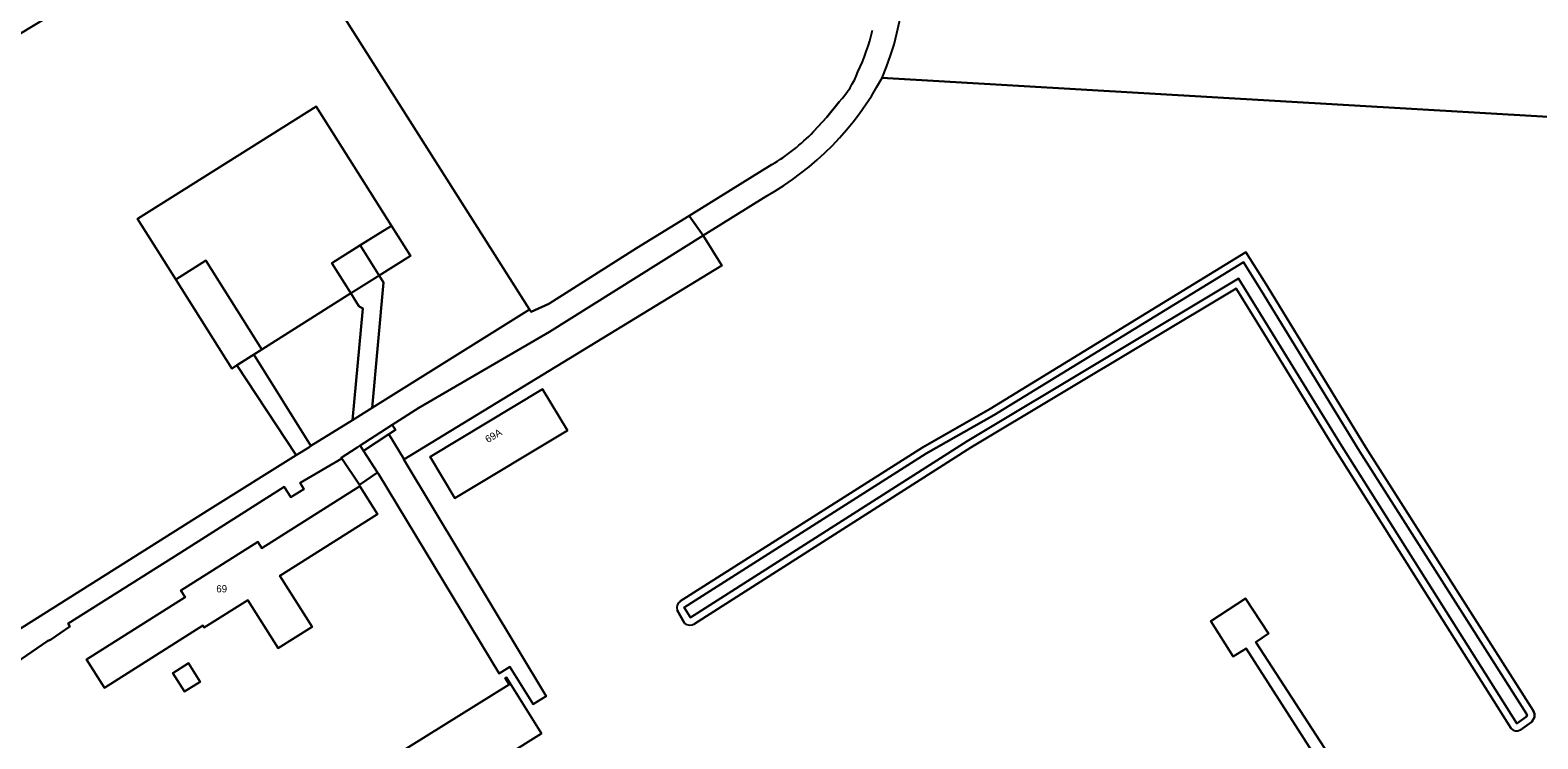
# Model space of a CAD drawing. Extents: x 158132 to 159664, y 385256 to 387218.
# Drawn here: x 158829.4 to 159037.8, y 386709.7 to 386807.7 of the extents above; entities that cross this region are included whole.
import ezdxf

# ---------------------------------------------------------------- set-up
doc = ezdxf.new("R2010")
doc.units = 0
for name, color, linetype in [('IMGEO_Gemengd_bos', 7, 'Continuous'), ('IMGEO_Groenvoorziening', 7, 'Continuous'), ('IMGEO_Loofbos', 7, 'Continuous'), ('IMGEO_Oever', 7, 'Continuous'), ('IMGEO_Open_loods', 7, 'Continuous'), ('IMGEO_Pand', 7, 'Continuous'), ('IMGEO_Pand_nummerreeks', 7, 'Continuous'), ('IMGEO_Pand_overbouw', 7, 'Continuous'), ('IMGEO_Parkeervlak_halfverhard', 7, 'Continuous'), ('IMGEO_Voetpad_gesloten', 7, 'Continuous'), ('IMGEO_Voetpad_halfverhard', 7, 'Continuous'), ('IMGEO_Voetpad_open', 7, 'Continuous'), ('IMGEO_Waterloop', 7, 'Continuous')]:
    doc.layers.add(name, color=color, linetype=linetype)

msp = doc.modelspace()

# ---------------------------------------------------------------- linework, layer by layer
at = {"layer": 'IMGEO_Gemengd_bos'}
for points in [[(158930.26, 386865.42), (158925.99, 386869.59), (158911.22, 386883.16), (158906.82, 386886.96), (158900.17, 386891.87), (158894.2, 386895.53), (158891.64, 386896.76), (158858.32, 386912.48), (158853.56, 386909.63), (158822.62, 386892.56), (158822.06, 386892.22), (158822.53, 386891.44), (158853.93, 386839), (158812.25, 386812.1), (158804.8, 386806.61), (158774.03, 386787.05), (158779.74, 386777.99), (158861.47, 386827.47), (158898.45, 386769.08), (158898.66, 386768.76), (158901.14, 386769.86), (158913.25, 386777.55), (158920.51, 386782.03), (158931.97, 386789.1)], [(158947.18, 386801.12), (159066.06, 386794.15), (159080.08, 386771.7), (159078.25, 386775.14), (159074.93, 386782.92), (159071.31, 386789.11), (159067.59, 386795.06), (159055.81, 386813.89), (159031.24, 386853.2), (159000, 386903.6)], [(159084.23, 386763.92), (159080.08, 386771.7), (159066.06, 386794.15), (158947.18, 386801.12)], [(158937.69, 386793.66), (158939.56, 386795.66), (158941.27, 386797.8)], [(158931.11, 386784.7), (158922.48, 386779.29), (158925.03, 386775.15), (158881.09, 386748.33), (158900.77, 386715.61), (158898.96, 386714.48), (158895.75, 386719.63), (158894.25, 386718.73), (158877.56, 386746.35), (158877.45, 386746.53), (158874.95, 386744.8), (158872.5, 386748.46), (158866.77, 386745.08), (158867.26, 386744.2), (158865.47, 386743.11), (158864.56, 386744.52), (158850.26, 386735.48), (158834.68, 386725.63), (158834.93, 386725.21), (158832.25, 386723.4), (158831.89, 386723.22), (158820.63, 386715.54)], [(158919.3, 386728.73), (158952.77, 386750), (158962.13, 386755.33), (158997.47, 386777.01), (159000, 386772.99), (159000.47, 386772.24), (159014.06, 386750), (159037.19, 386713.6), (159037.37, 386713.16), (159037.36, 386712.69), (159036.99, 386712.06), (159035.4, 386710.91)], [(159034.16, 386711.12), (159009.65, 386750), (159000, 386765.71), (158996.15, 386771.99), (158959.48, 386750)], [(158959.48, 386750), (158921.26, 386725.61)], [(159011.17, 386700.87), (158997.52, 386722.16), (158995.72, 386721.07), (158992.64, 386725.98), (158997.45, 386729.09), (159000.61, 386724.24), (158998.86, 386723.08), (159012.75, 386701.65)], [(158919.9, 386725.68), (158918.85, 386727.5)]]:
    msp.add_lwpolyline(points, dxfattribs=at)
for points in [[(158903.7, 386752.35), (158888.14, 386742.99), (158884.7, 386748.67), (158900.27, 386758.04)], [(158868.4, 386725.19), (158863.7, 386722.23), (158859.5, 386728.88), (158853.48, 386725.08), (158853.31, 386725.35), (158839.69, 386716.76), (158837.23, 386720.67), (158850.83, 386729.3), (158850.26, 386730.2), (158860.9, 386736.95), (158861.47, 386736.06), (158875.01, 386744.62), (158877.46, 386740.74), (158863.96, 386732.23)], [(158852.91, 386717.59), (158850.74, 386716.22), (158849.13, 386718.78), (158851.3, 386720.15)], [(158900.1, 386710.42), (158879.3, 386697.4), (158874.46, 386705.16), (158874.63, 386705.26), (158875.13, 386704.45), (158895.64, 386717.2), (158895.09, 386718.08), (158895.26, 386718.18)]]:
    msp.add_lwpolyline(points, close=True, dxfattribs=at)
for centre, radius, start, end in [((158915.43, 386815.16), 34.72, 336.1395, 19.0599), ((158916.08, 386814.9), 30.66, 334.9549, 346.4173), ((158911.05, 386820.41), 40.96, 299.3244, 331.8962), ((158932.18, 386806.35), 12.48, 316.7367, 339.1976), ((158918.94, 386811.37), 25.79, 300.3437, 316.6431), ((158919.9, 386727.81), 1.09, 122.962, 196.4586), ((158920.63, 386726.54), 1.13, 229.5335, 303.9903), ((159034.89, 386711.68), 0.919, 217.1084, 304.0415)]:
    msp.add_arc(centre, radius, start, end, dxfattribs=at)
at = {"layer": 'IMGEO_Groenvoorziening'}
msp.add_lwpolyline([(158873.76, 386771.3), (158861.45, 386763.54), (158860.33, 386762.83), (158868.24, 386750.19), (158873.97, 386753.77), (158875.41, 386769.19), (158874.88, 386769.51)], close=True, dxfattribs=at)
at = {"layer": 'IMGEO_Loofbos'}
msp.add_lwpolyline([(158858.01, 386761.37), (158857.29, 386760.92), (158849.54, 386773.22), (158844.27, 386781.59), (158868.97, 386797.12), (158879.37, 386780.65), (158882, 386776.49), (158877.66, 386773.76), (158878.28, 386772.78), (158876.69, 386755.48), (158881.12, 386758.25), (158898.45, 386769.08), (158861.47, 386827.47), (158779.74, 386777.99), (158817.59, 386717.84), (158825.55, 386722.84), (158825.32, 386723.2), (158854.25, 386741.43), (158866.2, 386748.91)], close=True, dxfattribs=at)
at = {"layer": 'IMGEO_Oever'}
for points in [[(159014.06, 386750), (159000.47, 386772.24), (159000, 386772.99), (158997.47, 386777.01), (158962.13, 386755.33), (158952.77, 386750), (158919.3, 386728.73)], [(158921.26, 386725.61), (158959.48, 386750), (158996.15, 386771.99), (159000, 386765.71), (159009.65, 386750), (159034.16, 386711.12)], [(159035.4, 386710.91), (159036.99, 386712.06), (159037.36, 386712.69), (159037.37, 386713.16), (159037.19, 386713.6), (159014.06, 386750)], [(158918.85, 386727.5), (158919.9, 386725.68)]]:
    msp.add_lwpolyline(points, dxfattribs=at)
msp.add_lwpolyline([(158958.95, 386750.86), (158920.7, 386726.45), (158919.81, 386727.85), (158953.29, 386749.14), (158962.65, 386754.46), (158997.15, 386775.62), (158999.15, 386772.45), (158999.61, 386771.71), (159013.2, 386749.47), (159036.29, 386713.13), (159036.36, 386712.97), (159036.23, 386712.75), (159034.92, 386711.81), (159010.51, 386750.53), (159000.86, 386766.24), (158996.48, 386773.37)], close=True, dxfattribs=at)
for centre, radius, start, end in [((158919.9, 386727.81), 1.09, 122.962, 196.4586), ((158920.63, 386726.54), 1.13, 229.5335, 303.9903), ((159034.89, 386711.68), 0.919, 217.1084, 304.0415)]:
    msp.add_arc(centre, radius, start, end, dxfattribs=at)
at = {"layer": 'IMGEO_Open_loods'}
msp.add_lwpolyline([(158900.1, 386710.42), (158895.26, 386718.18), (158895.09, 386718.08), (158895.64, 386717.2), (158875.13, 386704.45), (158874.63, 386705.26), (158874.46, 386705.16), (158879.3, 386697.4)], close=True, dxfattribs=at)
at = {"layer": 'IMGEO_Pand'}
for points in [[(158879.37, 386780.65), (158868.97, 386797.12), (158844.27, 386781.59), (158849.54, 386773.22), (158853.7, 386775.84), (158861.45, 386763.54), (158873.76, 386771.3), (158871.12, 386775.48), (158875.05, 386777.94)], [(158903.7, 386752.35), (158900.27, 386758.04), (158884.7, 386748.67), (158888.14, 386742.99)], [(158875.01, 386744.62), (158861.47, 386736.06), (158860.9, 386736.95), (158850.26, 386730.2), (158850.83, 386729.3), (158837.23, 386720.67), (158839.69, 386716.76), (158853.31, 386725.35), (158853.48, 386725.08), (158859.5, 386728.88), (158863.7, 386722.23), (158868.4, 386725.19), (158863.96, 386732.23), (158877.46, 386740.74)], [(158850.74, 386716.22), (158852.91, 386717.59), (158851.3, 386720.15), (158849.13, 386718.78)]]:
    msp.add_lwpolyline(points, close=True, dxfattribs=at)
at = {"layer": 'IMGEO_Pand_overbouw'}
for points in [[(158882, 386776.49), (158879.37, 386780.65), (158871.12, 386775.48), (158873.76, 386771.3)], [(158853.7, 386775.84), (158849.54, 386773.22), (158857.29, 386760.92), (158861.45, 386763.54)]]:
    msp.add_lwpolyline(points, close=True, dxfattribs=at)
at = {"layer": 'IMGEO_Parkeervlak_halfverhard'}
msp.add_lwpolyline([(158925.03, 386775.15), (158922.48, 386779.29), (158901.22, 386765.96), (158883.16, 386755.47), (158879.46, 386753.1), (158879.91, 386752.4), (158879, 386751.81), (158881.06, 386748.39), (158881.09, 386748.33)], close=True, dxfattribs=at)
at = {"layer": 'IMGEO_Voetpad_gesloten'}
msp.add_lwpolyline([(158820.63, 386715.54), (158831.89, 386723.22), (158832.25, 386723.4), (158834.93, 386725.21), (158834.68, 386725.63), (158850.26, 386735.48), (158864.56, 386744.52), (158865.47, 386743.11), (158867.26, 386744.2), (158866.77, 386745.08), (158872.5, 386748.46), (158872.43, 386748.56), (158874.65, 386750), (158875.04, 386750.25), (158877.14, 386751.61), (158879.46, 386753.1), (158883.16, 386755.47), (158901.22, 386765.96), (158922.48, 386779.29), (158920.51, 386782.03), (158913.25, 386777.55), (158901.14, 386769.86), (158898.66, 386768.76), (158898.45, 386769.08), (158881.12, 386758.25), (158876.69, 386755.48), (158873.97, 386753.77), (158868.24, 386750.19), (158867.94, 386750), (158866.2, 386748.91), (158854.25, 386741.43), (158825.32, 386723.2)], dxfattribs=at)
msp.add_lwpolyline([(158881.09, 386748.33), (158881.06, 386748.39), (158879, 386751.81), (158875.51, 386749.53), (158877.45, 386746.53), (158877.56, 386746.35), (158894.25, 386718.73), (158895.75, 386719.63), (158898.96, 386714.48), (158900.77, 386715.61)], close=True, dxfattribs=at)
at = {"layer": 'IMGEO_Voetpad_halfverhard'}
for points in [[(158882, 386776.49), (158879.37, 386780.65), (158875.05, 386777.94), (158877.58, 386773.89), (158877.66, 386773.76)], [(158853.7, 386775.84), (158849.54, 386773.22), (158857.29, 386760.92), (158858.01, 386761.37), (158860.33, 386762.83), (158861.45, 386763.54)], [(158875.51, 386749.53), (158875.04, 386750.25), (158874.65, 386750), (158872.43, 386748.56), (158872.5, 386748.46), (158874.95, 386744.8), (158877.45, 386746.53)], [(159012.14, 386697.47), (159015.42, 386699.56), (159013.8, 386702.29), (159012.75, 386701.65), (158998.86, 386723.08), (159000.61, 386724.24), (158997.45, 386729.09), (158992.64, 386725.98), (158995.72, 386721.07), (158997.52, 386722.16), (159011.17, 386700.87), (159010.3, 386700.29)]]:
    msp.add_lwpolyline(points, close=True, dxfattribs=at)
at = {"layer": 'IMGEO_Voetpad_open'}
for points in [[(158941.27, 386797.8), (158939.56, 386795.66), (158937.69, 386793.66)], [(158931.97, 386789.1), (158920.51, 386782.03), (158922.48, 386779.29), (158931.11, 386784.7)]]:
    msp.add_lwpolyline(points, dxfattribs=at)
for points in [[(158877.66, 386773.76), (158877.58, 386773.89), (158875.05, 386777.94), (158871.12, 386775.48), (158873.76, 386771.3), (158874.88, 386769.51), (158875.41, 386769.19), (158873.97, 386753.77), (158876.69, 386755.48), (158878.28, 386772.78)], [(158860.33, 386762.83), (158858.01, 386761.37), (158866.2, 386748.91), (158867.94, 386750), (158868.24, 386750.19)], [(158879.46, 386753.1), (158877.14, 386751.61), (158875.04, 386750.25), (158875.51, 386749.53), (158879, 386751.81), (158879.91, 386752.4)]]:
    msp.add_lwpolyline(points, close=True, dxfattribs=at)
for centre, radius, start, end in [((158915.43, 386815.16), 34.72, 336.1395, 19.0599), ((158916.08, 386814.9), 30.66, 334.9549, 346.4173), ((158911.05, 386820.41), 40.96, 299.3244, 331.8962), ((158932.18, 386806.35), 12.48, 316.7367, 339.1976), ((158918.94, 386811.37), 25.79, 300.3437, 316.6431)]:
    msp.add_arc(centre, radius, start, end, dxfattribs=at)
at = {"layer": 'IMGEO_Waterloop'}
msp.add_lwpolyline([(158958.95, 386750.86), (158996.48, 386773.37), (159000.86, 386766.24), (159010.51, 386750.53), (159034.92, 386711.81), (159036.23, 386712.75), (159036.36, 386712.97), (159036.29, 386713.13), (159013.2, 386749.47), (158999.61, 386771.71), (158999.15, 386772.45), (158997.15, 386775.62), (158962.65, 386754.46), (158953.29, 386749.14), (158919.81, 386727.85), (158920.7, 386726.45)], close=True, dxfattribs=at)

# ---------------------------------------------------------------- texts
at = {"layer": 'IMGEO_Pand_nummerreeks'}
msp.add_text('69A', height=1, rotation=30.8538, dxfattribs=at).set_placement((158892.7, 386750.57))
msp.add_text('69', height=1, dxfattribs=at).set_placement((158855.16, 386729.94))

doc.saveas('drawing.dxf')
